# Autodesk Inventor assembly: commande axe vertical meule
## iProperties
Shininess: 64.0
Length Units: 11269
Angle Units: 11279
Time Units: 11290
Mass Units: 11283
Length Display Precision: 3
Angle Display Precision: 2
Compacted: True
Created: 2004-12
Part Number: commande axe vertical meule
Document SubType Name: Assembly
Designer: LEGERET Philippe
Density: 0.0
Volumn: 0.0
Area: 0.0
PropertySet Name: Model Information
Control State: 0
Master: False
Checked Out: False
Author: LEGERET Philippe
